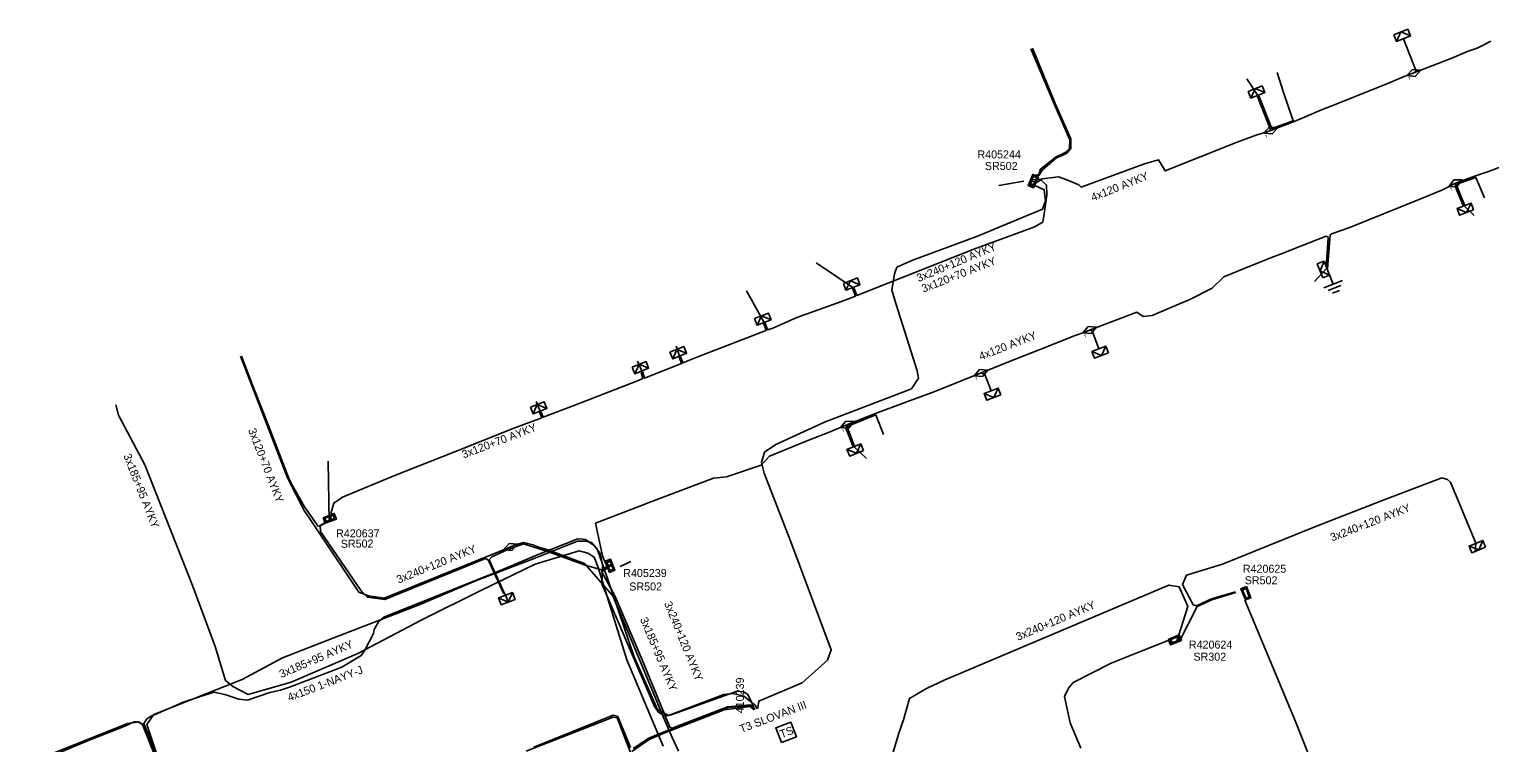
# Model space of a CAD drawing. Extents: x -540028 to -538776, y -1157064 to -1155670.
# Drawn here: x -540016.6 to -539834.1, y -1155929.9 to -1155840.8 of the extents above; entities that cross this region are included whole.
import ezdxf

# ---------------------------------------------------------------- set-up
doc = ezdxf.new("R2010")
doc.units = 0
for name, color, linetype in [('Vrstva 15', 7, 'Continuous'), ('Vrstva 19', 7, 'Continuous'), ('Vrstva 2', 7, 'Continuous'), ('Vrstva 25', 7, 'Continuous'), ('Vrstva 26', 7, 'Continuous'), ('Vrstva 27', 7, 'Continuous'), ('Vrstva 28', 7, 'Continuous'), ('Vrstva 29', 7, 'Continuous'), ('Vrstva 30', 7, 'Continuous'), ('Vrstva 31', 7, 'Continuous'), ('Vrstva 5', 7, 'Continuous'), ('Vrstva 52', 7, 'Continuous'), ('Vrstva 59', 7, 'Continuous'), ('Vrstva 6', 7, 'Continuous'), ('Vrstva 9', 7, 'Continuous')]:
    doc.layers.add(name, color=color, linetype=linetype)

# ---------------------------------------------------------------- blocks, each defined once
blk = doc.blocks.new('17')
at = {"layer": 'Vrstva 2'}
blk.add_lwpolyline([(-1.875, 0), (0, 0.9375), (1.875, 0), (0, -0.9375)], close=True, dxfattribs=at)
blk = doc.blocks.new('30')
at = {"layer": 'Vrstva 2'}
blk.add_lwpolyline([(-2, 0), (2, 0), (2, 4), (-2, 4)], close=True, dxfattribs=at)
blk.add_text('TS', height=2, dxfattribs=at).set_placement((-1.598, 1))
blk = doc.blocks.new('17.1')
at = {"layer": 'Vrstva 2'}
blk.add_lwpolyline([(-1.875, 0), (0, 0.9375), (1.875, 0), (0, -0.9375)], close=True, dxfattribs=at)
blk.add_text('T', height=0.75, dxfattribs=at).set_placement((-1.875, -1.35))
blk = doc.blocks.new('132')
at = {"layer": 'Vrstva 2'}
for points in [[(-1.5, 1.5), (1.5, 1.5), (1.5, 0), (-1.5, 0)], [(-1.1, 1.2), (1.1, 1.2), (1.1, 0.3), (-1.1, 0.3)]]:
    blk.add_lwpolyline(points, close=True, dxfattribs=at)
blk = doc.blocks.new('23')
at = {"layer": 'Vrstva 2'}
blk.add_lwpolyline([(1.875, -1.8), (-1.875, -1.8), (-1.875, 0), (1.875, 0)], close=True, dxfattribs=at)
blk.add_lwpolyline([(1.875, 0), (0, -1.8), (-1.875, 0)], dxfattribs=at)
blk = doc.blocks.new('11')
at = {"layer": 'Vrstva 2'}
for p, q in [((0, -4.3), (0, -1.3)), ((-2.5, -4.3), (2.5, -4.3)), ((-1.7, -5.3), (1.7, -5.3)), ((-0.9, -6.3), (0.9, -6.3))]:
    blk.add_line(p, q, dxfattribs=at)

msp = doc.modelspace()

# ---------------------------------------------------------------- linework, layer by layer
at = {"layer": 'Vrstva 5'}
for points in [[(-539891.28, -1155859.08), (-539890.47, -1155858.91), (-539890.26, -1155858.24), (-539888.29, -1155856.69), (-539887.68, -1155856.41), (-539887.1, -1155856.11), (-539886.63, -1155855.66), (-539886.59, -1155854.56), (-539888.57, -1155850.08), (-539891.48, -1155843.2)], [(-539891.34, -1155859.2), (-539890.42, -1155859), (-539890, -1155858.31), (-539888.27, -1155856.83), (-539887.62, -1155856.57), (-539886.98, -1155856.26), (-539886.48, -1155855.68), (-539886.45, -1155854.46), (-539888.42, -1155850.05), (-539891.25, -1155843.11)], [(-539834, -1155842.27), (-539835.04, -1155842.79), (-539835.71, -1155843.11), (-539836.81, -1155843.52), (-539837.7, -1155843.89), (-539838.87, -1155844.39), (-539843.6, -1155846.21), (-539844.84, -1155846.68), (-539847.28, -1155847.7), (-539854.08, -1155850.4), (-539855.13, -1155850.84), (-539857.28, -1155851.74), (-539858.37, -1155852.19), (-539861.48, -1155853.41)], [(-539861.48, -1155853.41), (-539863.15, -1155849.16), (-539863.1, -1155849.02)], [(-539861.48, -1155853.41), (-539863.45, -1155854.03), (-539865.7, -1155854.88), (-539874.68, -1155858.47), (-539875.52, -1155857.07), (-539877.27, -1155857.56), (-539885.16, -1155860.51), (-539885.46, -1155860.2), (-539886.95, -1155859.59), (-539888.03, -1155859.21), (-539890.04, -1155859.44), (-539890.71, -1155859.92), (-539891.54, -1155859.68)], [(-539838.42, -1155860), (-539835.92, -1155859.09), (-539834.3, -1155858.55), (-539829.64, -1155856.77)], [(-539978.93, -1155902.21), (-539978.89, -1155901.13), (-539978.57, -1155899.96), (-539977.48, -1155899.21), (-539970.85, -1155896.48), (-539963.54, -1155893.61), (-539955.92, -1155890.55), (-539952.57, -1155889.3), (-539952.82, -1155888.66), (-539952.79, -1155888.47), (-539952.64, -1155888.58), (-539952.39, -1155889.22), (-539948.44, -1155887.72), (-539940.6, -1155884.69), (-539939.93, -1155884.41), (-539940.14, -1155883.64), (-539940.09, -1155883.45), (-539939.95, -1155883.58), (-539939.75, -1155884.33), (-539935.11, -1155882.53), (-539935.38, -1155881.8), (-539935.35, -1155881.58), (-539935.19, -1155881.73), (-539934.93, -1155882.45), (-539932.88, -1155881.61), (-539924.67, -1155878.43), (-539924.53, -1155878.37), (-539924.83, -1155877.59), (-539924.8, -1155877.4), (-539924.65, -1155877.52), (-539924.34, -1155878.3), (-539923.7, -1155878.11), (-539920.7, -1155876.75), (-539915.12, -1155874.77), (-539913.37, -1155874.1), (-539913.72, -1155873.22), (-539913.69, -1155873.01), (-539913.53, -1155873.15), (-539913.19, -1155874.02), (-539907.19, -1155871.66), (-539898.57, -1155868.23), (-539891.08, -1155865.5), (-539889.98, -1155864.86), (-539889.85, -1155864.1), (-539889.45, -1155861.48), (-539889.49, -1155860.22), (-539890.32, -1155859.49), (-539891.5, -1155859.58)], [(-539925.55, -1155925.59), (-539925.57, -1155925.52), (-539925.46, -1155924.69), (-539920.02, -1155922.41), (-539916.86, -1155919.56), (-539916.41, -1155918.27), (-539921.44, -1155904.79), (-539924.77, -1155896.23), (-539925.12, -1155894.88), (-539924.73, -1155893.61), (-539923.32, -1155892.63), (-539917.26, -1155889.85), (-539906.39, -1155885.68), (-539905.49, -1155884.33), (-539905.68, -1155883.43), (-539908.3, -1155875.14), (-539908.85, -1155873.36), (-539908.5, -1155871.32), (-539908.19, -1155870.49), (-539906.33, -1155869.67), (-539898.13, -1155866.61), (-539889.99, -1155863.23), (-539889.65, -1155862.2), (-539889.79, -1155860.81), (-539891.67, -1155859.97)], [(-539914.39, -1155890.14), (-539910.89, -1155888.75), (-539907.1, -1155887.36), (-539905.83, -1155886.89), (-539903.8, -1155886.12), (-539902.43, -1155885.61), (-539897.69, -1155883.69), (-539895.67, -1155882.89), (-539894.66, -1155882.49), (-539889.24, -1155880.37), (-539888.12, -1155879.91), (-539885.91, -1155879.02), (-539884.74, -1155878.6), (-539884.12, -1155878.34), (-539878.22, -1155876.12), (-539877.44, -1155876.64), (-539876.29, -1155876.5), (-539871.53, -1155874.46), (-539868.81, -1155873.09), (-539867.36, -1155871.7), (-539863.88, -1155870.28), (-539861.06, -1155869.17), (-539859.94, -1155868.75), (-539858.81, -1155868.29), (-539854.55, -1155866.61), (-539854.35, -1155866.68), (-539854.31, -1155866.84), (-539854.57, -1155870.43), (-539854.49, -1155870.62), (-539854.39, -1155870.71), (-539854.08, -1155866.43), (-539853.77, -1155866.29), (-539851.73, -1155865.55), (-539842.67, -1155861.89), (-539840.11, -1155860.87), (-539838.42, -1155860)], [(-539838.42, -1155860), (-539838.4, -1155860.5), (-539837.46, -1155862.77), (-539837.34, -1155862.81)], [(-539935.5, -1155930.94), (-539936.28, -1155929.23), (-539937.43, -1155926.53), (-539941.81, -1155916), (-539943.7, -1155911.53), (-539947.25, -1155907.51), (-539951.96, -1155905.76), (-539952.86, -1155905.48), (-539953.67, -1155905.18), (-539954.86, -1155904.86), (-539956.03, -1155905.22), (-539956.94, -1155905.62), (-539972.25, -1155911.81), (-539974.22, -1155911.54), (-539975.45, -1155911.06), (-539980.4, -1155903.65), (-539981.7, -1155901.66), (-539982.22, -1155900.98), (-539984.36, -1155896.78), (-539990.22, -1155881.62)], [(-539979.3, -1155902.33), (-539979.48, -1155902.3), (-539980.34, -1155902.79), (-539980.6, -1155902.83), (-539980.65, -1155902.68), (-539982.23, -1155900.41), (-539983.83, -1155897.56), (-539984.21, -1155896.76), (-539987.26, -1155888.88), (-539988.71, -1155885.22), (-539990.1, -1155881.58)], [(-540005.79, -1155887.68), (-540005.44, -1155888.98), (-540002.16, -1155895.19), (-539996.22, -1155910.25), (-539993.37, -1155917.87), (-539992.07, -1155922.1), (-539991.17, -1155922.86), (-539989.24, -1155923.86), (-539983.88, -1155922.3), (-539975.57, -1155918.75), (-539967.54, -1155914.52), (-539960.17, -1155910.88), (-539953.38, -1155907.59), (-539947.91, -1155905.93), (-539946.82, -1155906.19), (-539946.03, -1155906.69), (-539945.56, -1155907.88), (-539941.93, -1155919.51), (-539937.39, -1155930.32)], [(-539943.88, -1155907.2), (-539944.6, -1155907.46), (-539944.97, -1155906.52), (-539945.86, -1155902.46), (-539940.1, -1155900.24), (-539938.95, -1155899.8), (-539931.12, -1155896.85), (-539929.49, -1155896.67), (-539925.16, -1155895.2), (-539924.11, -1155894.09), (-539919.13, -1155892.03), (-539916.74, -1155891.12), (-539914.39, -1155890.14)], [(-539914.39, -1155890.14), (-539914.57, -1155890.58), (-539913.71, -1155892.82), (-539913.57, -1155892.89)], [(-539865.91, -1155911.02), (-539868.91, -1155911.92), (-539870.76, -1155912.77), (-539871.17, -1155912.68), (-539872.52, -1155910.14), (-539872.03, -1155908.94), (-539867.53, -1155907.6), (-539855.99, -1155902.92), (-539847.66, -1155899.67), (-539840.1, -1155896.81), (-539839.41, -1155897.02), (-539839.03, -1155897.35), (-539835.85, -1155904.97)], [(-539943.77, -1155907.53), (-539945.11, -1155908.29), (-539947.28, -1155907.66), (-539951.72, -1155906.03), (-539954.87, -1155905.02), (-539956.89, -1155905.79), (-539958.82, -1155906.67), (-539959.15, -1155907.04), (-539957.28, -1155911.16), (-539957.09, -1155911.47), (-539957.37, -1155911.21), (-539959.29, -1155907.05), (-539959.61, -1155906.87), (-539972.19, -1155911.98), (-539974.36, -1155911.72), (-539975.12, -1155910.91), (-539980.22, -1155903.48), (-539980.28, -1155902.81), (-539979.5, -1155902.36), (-539979.41, -1155902.37)], [(-539925.98, -1155925.75), (-539926.25, -1155925.02), (-539926.87, -1155923.83), (-539927.37, -1155923.51), (-539928.17, -1155923.44), (-539936.4, -1155926.42), (-539936.8, -1155926.48), (-539937.37, -1155926.47), (-539938.03, -1155926.04), (-539938.48, -1155925.37), (-539945.08, -1155910.02), (-539944.97, -1155907.64), (-539945.29, -1155906.24), (-539946, -1155905.29), (-539947.12, -1155904.52), (-539947.46, -1155904.45), (-539948.05, -1155904.41), (-539953.02, -1155906.39), (-539958.35, -1155908.61), (-539960.99, -1155909.65), (-539972.29, -1155914.2), (-539972.99, -1155914.79), (-539973.52, -1155915.75), (-539973.61, -1155916.25), (-539974.66, -1155918.32), (-539975.14, -1155918.99), (-539977.54, -1155920.43), (-539984.11, -1155922.96), (-539985.22, -1155923.32), (-539986.54, -1155923.59), (-539989.33, -1155924.57), (-539990.41, -1155924.44), (-539992.16, -1155923.88), (-539993.55, -1155923.56), (-539997.38, -1155924.82), (-539998.65, -1155925.38), (-540001.37, -1155926.56), (-540001.93, -1155926.91), (-540002.3, -1155927.48), (-540000.64, -1155931.61)], [(-539926, -1155925.76), (-539926.46, -1155925.17), (-539929.35, -1155925.39), (-539936.29, -1155928.07), (-539936.59, -1155927.94), (-539940.03, -1155919.51), (-539943.42, -1155911.61), (-539945.07, -1155908.52), (-539943.74, -1155907.61)], [(-539923.21, -1155932.13), (-539920.48, -1155933.29), (-539917.96, -1155933.77), (-539915.09, -1155934.22), (-539913.44, -1155934.2), (-539911.31, -1155934.66), (-539910.61, -1155934.6), (-539909.58, -1155933.81), (-539908.94, -1155932.04), (-539907.91, -1155928.58), (-539907.39, -1155927.03), (-539906.62, -1155924.35), (-539904.52, -1155923.13), (-539902.28, -1155922.05), (-539874.21, -1155910.19), (-539872.95, -1155910.4), (-539871.83, -1155912.86), (-539873.27, -1155917.34)], [(-539872.88, -1155917.18), (-539870.67, -1155912.86), (-539868.87, -1155912.03), (-539865.86, -1155911.13)], [(-539864.72, -1155912.09), (-539858.4, -1155927.24), (-539845.14, -1155960.66), (-539843.86, -1155962.22), (-539842.78, -1155963.39), (-539840.09, -1155969.77)], [(-539873.57, -1155917.46), (-539874.09, -1155917.04), (-539877.68, -1155918.43), (-539881.42, -1155919.95), (-539886.16, -1155922.38), (-539886.77, -1155923.05), (-539887.27, -1155924.13), (-539886.55, -1155927.38), (-539885.24, -1155930.57)], [(-539941.33, -1155930.97), (-539939.17, -1155929.47), (-539937.21, -1155928.66), (-539929.78, -1155925.79), (-539926.52, -1155925.36), (-539926.05, -1155925.78)], [(-539925.97, -1155925.7), (-539926.48, -1155925.24), (-539929.29, -1155925.47), (-539937.29, -1155928.53), (-539939.2, -1155929.31), (-539941.17, -1155930.62)], [(-540000.83, -1155931.68), (-540002.5, -1155927.53), (-540003.09, -1155927.28), (-540003.49, -1155927.29), (-540004.77, -1155927.86), (-540008.91, -1155929.5), (-540013.7, -1155931.47)], [(-539954.51, -1155930.95), (-539943.67, -1155926.69), (-539943.15, -1155926.79), (-539936.08, -1155945.19)], [(-539941.49, -1155930.5), (-539943.08, -1155926.61), (-539943.66, -1155926.44), (-539953.55, -1155930.43)]]:
    msp.add_lwpolyline(points, dxfattribs=at)
at = {"layer": 'Vrstva 52'}
for points in [[(-539843.6, -1155846.21), (-539843.32, -1155846.01), (-539844.9, -1155841.95)], [(-539863.1, -1155849.02), (-539862.96, -1155849.09), (-539861.36, -1155853.16), (-539858.69, -1155852.2), (-539859.92, -1155848.53), (-539860.68, -1155846.17)], [(-539837.34, -1155862.81), (-539837.28, -1155862.69), (-539838.2, -1155860.46), (-539838.22, -1155860.13), (-539835.86, -1155859.27), (-539834.78, -1155861.81)], [(-539884.12, -1155878.34), (-539883.82, -1155878.45), (-539882.96, -1155880.69)], [(-539897.69, -1155883.69), (-539897.2, -1155883.87), (-539896.43, -1155885.93)], [(-539913.57, -1155892.89), (-539913.52, -1155892.75), (-539914.37, -1155890.56), (-539914.32, -1155890.33), (-539910.82, -1155888.94), (-539909.87, -1155891.4)], [(-539979.12, -1155902.28), (-539979.28, -1155894.7)]]:
    msp.add_lwpolyline(points, dxfattribs=at)
at = {"layer": 'Vrstva 59'}
for points in [[(-539863.1, -1155849.02), (-539864.48, -1155846.96)], [(-539892.33, -1155859.74), (-539895.46, -1155860.28)], [(-539837.34, -1155862.81), (-539836.06, -1155864.05)], [(-539913.69, -1155873.01), (-539918.29, -1155869.94)], [(-539854.49, -1155870.62), (-539856.04, -1155872.26)], [(-539924.8, -1155877.4), (-539927, -1155873.46)], [(-539935.35, -1155881.58), (-539935.8, -1155880.37)], [(-539940.09, -1155883.45), (-539940.6, -1155882.23)], [(-539952.79, -1155888.47), (-539953.29, -1155887.28)], [(-539913.57, -1155892.89), (-539912.01, -1155894.4)], [(-539835.85, -1155904.97), (-539835.94, -1155906.08)], [(-539942.78, -1155907.89), (-539941.45, -1155907.25)], [(-539957.09, -1155911.47), (-539956.73, -1155912.41)]]:
    msp.add_lwpolyline(points, dxfattribs=at)
at = {"layer": 'Vrstva 9'}
for points in [[(-540000.53, -1155931.74), (-540001.9, -1155927.61), (-540001.03, -1155926.36), (-539990.02, -1155921.98), (-539984.95, -1155919.3), (-539979.1, -1155916.97), (-539967.89, -1155912.66), (-539960.73, -1155909.63), (-539953.51, -1155906.89), (-539948.09, -1155904.7), (-539947.16, -1155904.7), (-539946.31, -1155904.88), (-539945.7, -1155905.57), (-539944.86, -1155907.93), (-539941.01, -1155919.16), (-539938.1, -1155925.75), (-539936.72, -1155926.48), (-539929.82, -1155923.85), (-539928.7, -1155923.73), (-539927.31, -1155924.08), (-539925.91, -1155925.18), (-539925.67, -1155925.63)], [(-540016.61, -1155932.38), (-540004.35, -1155927.48), (-540002.93, -1155927.29), (-540002.15, -1155927.87), (-540000.6, -1155931.77)]]:
    msp.add_lwpolyline(points, dxfattribs=at)

# ---------------------------------------------------------------- block references
at = {"layer": 'Vrstva 15', "xscale": 0.49999999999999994, "yscale": 0.5000000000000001, "rotation": 21.481505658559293}
msp.add_blockref('11', (-539854.49, -1155870.62), dxfattribs=at)
at = {"layer": 'Vrstva 19'}
for name, p, xscale, yscale, rotation in [('17.1', (-539843.6, -1155846.21), 0.5, 0.5, 20.986044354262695), ('17.1', (-539861.48, -1155853.41), 0.5, 0.5, 21.50881386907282), ('17.1', (-539838.42, -1155860), 0.49999999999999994, 0.49999999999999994, 27.40162223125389), ('17.1', (-539884.12, -1155878.34), 0.49999999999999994, 0.5000000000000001, 22.750974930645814), ('17.1', (-539897.69, -1155883.69), 0.5, 0.5, 22.05106394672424), ('17.1', (-539914.39, -1155890.14), 0.49999999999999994, 0.5000000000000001, 22.66478609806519), ('17', (-539956.47, -1155905.45), 0.5, 0.5, 22.007586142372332)]:
    msp.add_blockref(name, p, dxfattribs=dict(at, xscale=xscale, yscale=yscale, rotation=rotation))
at = {"layer": 'Vrstva 25', "xscale": 0.5000000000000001, "yscale": 0.4999999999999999, "rotation": 20.738136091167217}
msp.add_blockref('30', (-539921.69, -1155929.52), dxfattribs=at)
at = {"layer": 'Vrstva 28'}
for p, xscale, yscale, rotation in [((-539891.5, -1155859.58), 0.5, 0.5000000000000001, -113.58703049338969), ((-539978.93, -1155902.21), 0.49999999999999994, 0.5000000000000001, 21.07749416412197), ((-539943.7, -1155907.64), 0.49999999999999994, 0.5000000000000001, 111.57257499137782), ((-539864.94, -1155911.35), 0.5, 0.5, -68.55913061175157), ((-539873.34, -1155917.39), 0.5, 0.5, 22.084027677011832)]:
    msp.add_blockref('132', p, dxfattribs=dict(at, xscale=xscale, yscale=yscale, rotation=rotation))
at = {"layer": 'Vrstva 31'}
for p, xscale, yscale, rotation in [((-539844.9, -1155841.94), 0.5000000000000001, 0.5, -158.30884452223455), ((-539863.1, -1155849.02), 0.5, 0.5000000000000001, -158.21904727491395), ((-539837.34, -1155862.81), 0.49999999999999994, 0.5000000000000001, 21.20922500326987), ((-539854.49, -1155870.62), 0.49999999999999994, 0.5000000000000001, -68.51849440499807), ((-539913.69, -1155873.01), 0.5, 0.5, -158.67935631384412), ((-539924.8, -1155877.4), 0.5, 0.5, -158.6148178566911), ((-539935.35, -1155881.58), 0.49999999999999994, 0.5, -157.4235878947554), ((-539882.96, -1155880.69), 0.5, 0.5000000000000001, 21.068974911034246), ((-539940.09, -1155883.45), 0.5, 0.5, -158.43544117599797), ((-539896.43, -1155885.93), 0.5, 0.5000000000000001, 21.068974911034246), ((-539952.79, -1155888.47), 0.5, 0.5, -157.9326110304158), ((-539913.57, -1155892.89), 0.49999999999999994, 0.5000000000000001, 22.281886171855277), ((-539835.85, -1155904.97), 0.49999999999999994, 0.5000000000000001, 22.07613342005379), ((-539957.09, -1155911.47), 0.5, 0.5, 20.937905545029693)]:
    msp.add_blockref('23', p, dxfattribs=dict(at, xscale=xscale, yscale=yscale, rotation=rotation))

# ---------------------------------------------------------------- texts
at = {"layer": 'Vrstva 26'}
msp.add_text('410239', height=1, rotation=90, dxfattribs=at).set_placement((-539927.32, -1155926.2))
at = {"layer": 'Vrstva 27'}
msp.add_text('T3 SLOVAN III', height=1, rotation=20.738, dxfattribs=at).set_placement((-539927.64, -1155928.67))
at = {"layer": 'Vrstva 29'}
for s, rotation, p in [('R405244', 0.004, (-539898.14, -1155856.9)), ('R405239', 0.042, (-539942.39, -1155909.19))]:
    msp.add_text(s, height=1, rotation=rotation, dxfattribs=at).set_placement(p)
for s, p in [('R420637', (-539978.27, -1155904.23)), ('R420625', (-539864.98, -1155908.65)), ('R420624', (-539871.72, -1155918.13))]:
    msp.add_text(s, height=1, dxfattribs=at).set_placement(p)
at = {"layer": 'Vrstva 30'}
for s, rotation, p in [('SR502', 0.004, (-539897.21, -1155858.34)), ('SR502', 0.632, (-539977.68, -1155905.54)), ('SR502', 359.909, (-539864.74, -1155910.09)), ('SR502', 0.042, (-539941.64, -1155910.87)), ('SR302', 359.777, (-539871.15, -1155919.63))]:
    msp.add_text(s, height=1, rotation=rotation, dxfattribs=at).set_placement(p)
at = {"layer": 'Vrstva 6'}
for s, rotation, p in [('4x120 AYKY', 21.79, (-539883.72, -1155862.28)), ('3x240+120 AYKY', 22.511, (-539905.48, -1155872.36)), ('3x120+70 AYKY', 21.342, (-539904.89, -1155873.67)), ('4x120 AYKY', 21.363, (-539897.72, -1155882.13)), ('3x120+70 AYKY', 291.205, (-539989.28, -1155890.82)), ('3x120+70 AYKY', 20.857, (-539962.33, -1155894.39)), ('3x185+95 AYKY', 291.53, (-540004.87, -1155894.02)), ('3x240+120 AYKY', 21.255, (-539853.82, -1155904.76)), ('3x240+120 AYKY', 22.098, (-539970.47, -1155910.02)), ('3x240+120 AYKY', 292.213, (-539937.31, -1155912.47)), ('3x240+120 AYKY', 22.922, (-539893.07, -1155917.16)), ('3x185+95 AYKY', 292.791, (-539940.32, -1155914.46)), ('3x185+95 AYKY', 23.134, (-539985.11, -1155921.81)), ('4x150 1-NAYY-J', 21.061, (-539984.11, -1155924.74))]:
    msp.add_text(s, height=1, rotation=rotation, dxfattribs=at).set_placement(p)

doc.saveas('drawing.dxf')
